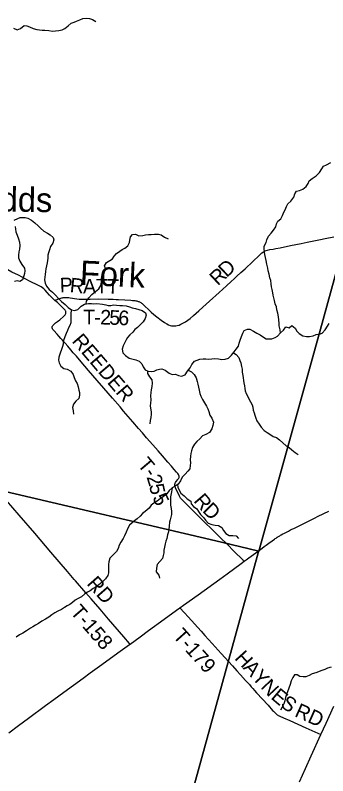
# Model space of a CAD drawing. Extents: x 1442749 to 1756758, y 235267 to 677782.
# Drawn here: x 1566168 to 1572579, y 484946 to 500562 of the extents above; entities that cross this region are included whole.
import ezdxf

# ---------------------------------------------------------------- set-up
doc = ezdxf.new("R2010")
doc.units = 0
for name, color, linetype in [('GM_X_County_Road', 7, 'Continuous'), ('GM_X_Minor_River', 7, 'Continuous'), ('GM_X_Minor_River_Text', 7, 'Continuous'), ('GM_X_Township', 7, 'Continuous'), ('GM_X_Township_Road', 7, 'Continuous'), ('GM_X_Township_Road_Text', 7, 'Continuous'), ('GM_X_US_Route', 7, 'Continuous')]:
    doc.layers.add(name, color=color, linetype=linetype)

msp = doc.modelspace()

# ---------------------------------------------------------------- linework, layer by layer
at = {"layer": 'GM_X_County_Road'}
for points in [[(1571367, 489719), (1571435, 489770), (1571483, 489803), (1571502, 489817), (1571518, 489828), (1571533, 489838), (1571539, 489842), (1571544, 489845), (1571557, 489853), (1571570, 489861), (1571580, 489867), (1571594, 489875), (1571609, 489883), (1571625, 489892), (1571660, 489912), (1571690, 489929), (1571718, 489944), (1571743, 489957), (1571770, 489971), (1571794, 489984), (1571817, 489995), (1571840, 490007), (1571879, 490026), (1572100, 490135), (1572305, 490236), (1572384, 490275), (1572599, 490381)], [(1570863, 489349), (1570904, 489379), (1570960, 489420), (1571052, 489488), (1571150, 489559), (1571232, 489620), (1571274, 489651), (1571315, 489681), (1571367, 489719)], [(1569547, 488394), (1569621, 488449), (1569918, 488660), (1570366, 488986), (1570515, 489094), (1570801, 489304), (1570863, 489349)], [(1568523, 487651), (1568730, 487801), (1568902, 487927), (1569226, 488161), (1569479, 488344), (1569547, 488394)], [(1566036, 485831), (1566237, 485980), (1566438, 486126), (1566790, 486386), (1566959, 486510), (1567168, 486663), (1567563, 486950), (1567708, 487058), (1567945, 487229), (1568275, 487472), (1568512, 487643), (1568523, 487651)]]:
    msp.add_lwpolyline(points, dxfattribs=at)
at = {"layer": 'GM_X_Minor_River'}
for points in [[(1566134, 500299), (1566209, 500259), (1566278, 500289), (1566349, 500350), (1566409, 500345), (1566462, 500324), (1566534, 500291), (1566608, 500270), (1566666, 500263), (1566722, 500256), (1566778, 500256), (1566858, 500247), (1566930, 500236), (1566996, 500241), (1567062, 500248), (1567132, 500261), (1567183, 500288), (1567253, 500347), (1567316, 500397), (1567375, 500420), (1567425, 500437), (1567495, 500468), (1567552, 500494), (1567624, 500503), (1567688, 500494), (1567750, 500471), (1567821, 500432)], [(1571607, 494037), (1571599, 494102), (1571584, 494181), (1571579, 494231), (1571572, 494309), (1571565, 494372), (1571554, 494442), (1571535, 494512), (1571524, 494571), (1571501, 494637), (1571486, 494707), (1571473, 494758), (1571461, 494812), (1571452, 494864), (1571435, 494931), (1571426, 494983), (1571415, 495049), (1571408, 495113), (1571390, 495172), (1571374, 495246), (1571358, 495310), (1571347, 495371), (1571332, 495453), (1571317, 495525), (1571304, 495586), (1571289, 495648), (1571282, 495698), (1571273, 495769), (1571276, 495821), (1571313, 495896), (1571328, 495950), (1571363, 496026), (1571418, 496089), (1571463, 496145), (1571510, 496216), (1571529, 496276), (1571551, 496334), (1571614, 496379), (1571653, 496449), (1571680, 496517), (1571707, 496568), (1571732, 496632), (1571761, 496688), (1571824, 496747), (1571885, 496823), (1571902, 496893), (1571937, 496948), (1572001, 496965), (1572068, 496991), (1572136, 497044), (1572173, 497105), (1572196, 497159), (1572259, 497212), (1572342, 497267), (1572407, 497329), (1572454, 497410), (1572489, 497462), (1572553, 497489), (1572642, 497540)], [(1566148, 496352), (1566221, 496385), (1566271, 496406), (1566321, 496411), (1566375, 496411), (1566427, 496392), (1566503, 496351), (1566572, 496300), (1566639, 496239), (1566684, 496188), (1566756, 496127), (1566827, 496086), (1566883, 496055), (1566944, 496000), (1566963, 495950), (1566940, 495882), (1566891, 495816), (1566868, 495748), (1566849, 495685), (1566839, 495633), (1566838, 495572), (1566822, 495480), (1566797, 495357), (1566790, 495302), (1566779, 495236), (1566772, 495184), (1566771, 495130), (1566782, 495062), (1566809, 494996), (1566864, 494929), (1566932, 494872), (1566995, 494811), (1567052, 494746), (1567117, 494683), (1567190, 494620), (1567255, 494559), (1567321, 494510), (1567383, 494497), (1567455, 494522), (1567522, 494587), (1567591, 494628), (1567671, 494641), (1567729, 494640), (1567781, 494638), (1567843, 494641), (1567955, 494631), (1568023, 494618), (1568077, 494605), (1568131, 494605), (1568181, 494612), (1568243, 494611), (1568311, 494604), (1568367, 494600), (1568441, 494592), (1568511, 494576), (1568565, 494557), (1568637, 494542), (1568702, 494519), (1568774, 494496), (1568839, 494453), (1568851, 494400), (1568834, 494333), (1568791, 494269), (1568728, 494202), (1568673, 494150), (1568622, 494109), (1568581, 494057), (1568517, 493998), (1568474, 493947), (1568443, 493895)], [(1566164, 496221), (1566174, 496171), (1566183, 496113), (1566208, 496044), (1566237, 495972), (1566252, 495901), (1566261, 495831), (1566252, 495761), (1566243, 495701), (1566234, 495635), (1566237, 495583), (1566264, 495512), (1566305, 495443), (1566358, 495366), (1566365, 495312), (1566359, 495260), (1566342, 495208), (1566319, 495131), (1566262, 495093), (1566208, 495106), (1566156, 495095)], [(1567622, 494633), (1567632, 494690), (1567677, 494757), (1567736, 494827), (1567813, 494886), (1567880, 494941), (1567927, 495012), (1567940, 495084), (1567937, 495151), (1567943, 495203), (1567962, 495254), (1568005, 495310), (1568016, 495364), (1568001, 495418), (1568040, 495484), (1568106, 495523), (1568161, 495560), (1568198, 495616), (1568248, 495668), (1568311, 495715), (1568364, 495754), (1568416, 495781), (1568479, 495825), (1568510, 495892), (1568517, 495946), (1568534, 496010), (1568573, 496062), (1568633, 496067), (1568702, 496030), (1568784, 496039), (1568841, 496052), (1568899, 496058), (1568955, 496061), (1569023, 496068), (1569107, 496067), (1569161, 496052), (1569232, 496007), (1569302, 495972)], [(1567321, 494510), (1567308, 494452), (1567305, 494379), (1567308, 494309), (1567307, 494245), (1567290, 494193), (1567263, 494141), (1567237, 494086), (1567214, 494024), (1567185, 493956), (1567160, 493884), (1567152, 493810), (1567140, 493758), (1567119, 493696), (1567088, 493623), (1567062, 493543), (1567052, 493481), (1567067, 493427), (1567100, 493354), (1567167, 493311), (1567235, 493294), (1567307, 493255), (1567356, 493188), (1567377, 493122), (1567406, 493055), (1567435, 493003), (1567460, 492930), (1567475, 492864), (1567484, 492814), (1567488, 492763), (1567469, 492695), (1567410, 492640), (1567363, 492573), (1567344, 492505), (1567355, 492436), (1567364, 492370)], [(1568443, 493895), (1568414, 493843), (1568379, 493776), (1568362, 493704), (1568373, 493633), (1568430, 493572), (1568506, 493519), (1568557, 493504), (1568639, 493483), (1568709, 493456), (1568766, 493405), (1568789, 493341), (1568830, 493282), (1568892, 493253), (1568966, 493246), (1569016, 493254), (1569075, 493279), (1569125, 493296), (1569175, 493302), (1569245, 493277), (1569324, 493213), (1569388, 493182), (1569452, 493194), (1569517, 493167), (1569579, 493152), (1569652, 493181), (1569699, 493252), (1569756, 493322), (1569793, 493393), (1569846, 493459), (1569900, 493480), (1569953, 493498), (1570021, 493509), (1570079, 493506), (1570133, 493501), (1570199, 493510), (1570253, 493511), (1570337, 493506), (1570407, 493495), (1570477, 493500), (1570540, 493518), (1570607, 493581), (1570658, 493648), (1570700, 493702), (1570747, 493765), (1570760, 493827), (1570779, 493893), (1570810, 493965), (1570837, 494035), (1570864, 494086), (1570933, 494116), (1570983, 494113), (1571054, 494076), (1571124, 494031), (1571191, 493998), (1571257, 493953), (1571316, 493920), (1571368, 493915), (1571432, 493916), (1571497, 493942), (1571547, 493971), (1571608, 494038), (1571671, 494095), (1571718, 494161), (1571788, 494146), (1571841, 494189), (1571910, 494136), (1571947, 494076), (1571992, 494025), (1572064, 493980), (1572144, 493965), (1572206, 493966), (1572276, 493981), (1572338, 494006), (1572411, 494013), (1572461, 494035), (1572522, 494100), (1572571, 494179), (1572610, 494235)], [(1570643, 493629), (1570697, 493598), (1570756, 493531), (1570775, 493474), (1570792, 493424), (1570809, 493352), (1570821, 493297), (1570826, 493231), (1570837, 493163), (1570859, 493014), (1570868, 492954), (1570877, 492898), (1570884, 492847), (1570903, 492797), (1570937, 492732), (1570968, 492674), (1570995, 492623), (1571026, 492561), (1571039, 492511), (1571051, 492456), (1571068, 492398), (1571081, 492348), (1571100, 492289), (1571125, 492233), (1571171, 492162), (1571214, 492101), (1571271, 492036), (1571338, 491997), (1571408, 491946), (1571459, 491909), (1571525, 491889), (1571586, 491846), (1571655, 491780), (1571723, 491721), (1571786, 491689), (1571838, 491638), (1571907, 491583), (1571968, 491542)], [(1569717, 493274), (1569781, 493239), (1569838, 493182), (1569879, 493114), (1569898, 493041), (1569913, 492989), (1569928, 492925), (1569940, 492866), (1569956, 492794), (1569974, 492742), (1570007, 492671), (1570050, 492602), (1570091, 492533), (1570116, 492479), (1570137, 492427), (1570162, 492352), (1570201, 492287), (1570232, 492203), (1570223, 492139), (1570200, 492071), (1570151, 491997), (1570080, 491952), (1570012, 491925), (1569953, 491864), (1569890, 491807), (1569845, 491753), (1569806, 491683), (1569785, 491620), (1569770, 491566), (1569764, 491508), (1569757, 491436), (1569760, 491373), (1569759, 491317), (1569746, 491251), (1569711, 491200), (1569654, 491138), (1569591, 491075), (1569560, 491005), (1569509, 490934), (1569448, 490895), (1569386, 490859), (1569327, 490804), (1569278, 490736), (1569201, 490675), (1569148, 490638), (1569080, 490583), (1569011, 490540), (1568954, 490502), (1568913, 490439), (1568836, 490370), (1568780, 490328), (1568733, 490277), (1568672, 490224), (1568613, 490180), (1568563, 490141), (1568512, 490091), (1568475, 490032), (1568442, 489946), (1568411, 489870), (1568380, 489819), (1568335, 489745), (1568302, 489681), (1568277, 489610), (1568246, 489552), (1568173, 489479), (1568108, 489417), (1568089, 489339), (1568082, 489287), (1568081, 489237), (1568082, 489183), (1568079, 489113), (1568064, 489055), (1568017, 488988), (1567952, 488924), (1567884, 488869), (1567827, 488828), (1567768, 488793), (1567702, 488745), (1567647, 488714), (1567594, 488679), (1567526, 488622), (1567459, 488588), (1567396, 488555), (1567342, 488504), (1567287, 488464), (1567233, 488435), (1567176, 488402), (1567117, 488362), (1567045, 488327), (1566980, 488294), (1566918, 488249), (1566859, 488200), (1566786, 488164), (1566714, 488123), (1566647, 488072), (1566586, 488041), (1566530, 488006), (1566479, 487974), (1566398, 487919), (1566326, 487876), (1566253, 487837)], [(1568878, 493260), (1568883, 493203), (1568920, 493139), (1568968, 493076), (1568979, 493004), (1568970, 492936), (1568957, 492868), (1568948, 492814), (1568945, 492744), (1568952, 492665), (1568945, 492593), (1568938, 492541), (1568943, 492491), (1568958, 492419), (1568959, 492368), (1568946, 492302), (1568935, 492238), (1568930, 492172)], [(1569384, 490857), (1569373, 490779), (1569351, 490675), (1569352, 490619), (1569353, 490561), (1569353, 490505), (1569366, 490431), (1569375, 490370), (1569370, 490310), (1569361, 490258), (1569344, 490202), (1569329, 490150), (1569322, 490074), (1569317, 490008), (1569311, 489956), (1569294, 489896), (1569275, 489820), (1569260, 489763), (1569243, 489709), (1569228, 489641), (1569219, 489577), (1569216, 489525), (1569205, 489467), (1569187, 489409), (1569134, 489343), (1569079, 489282), (1569064, 489206), (1569056, 489132), (1569114, 489067), (1569129, 489001)], [(1569496, 490925), (1569506, 490872), (1569525, 490821), (1569568, 490749), (1569632, 490694), (1569695, 490633), (1569768, 490581), (1569775, 490527), (1569823, 490474), (1569896, 490427), (1569929, 490371), (1569970, 490312), (1570034, 490243), (1570073, 490192), (1570128, 490134), (1570200, 490103), (1570266, 490094), (1570334, 490085), (1570405, 490042), (1570438, 489985), (1570491, 489922), (1570559, 489881), (1570633, 489882), (1570701, 489875), (1570746, 489820)], [(1566253, 487837), (1566186, 487794)], [(1572646, 487177), (1572573, 487154), (1572517, 487128), (1572438, 487099), (1572388, 487078), (1572332, 487063), (1572259, 487038), (1572195, 487002), (1572128, 486979), (1572072, 486976), (1572008, 486985), (1571951, 487018), (1571897, 487019), (1571860, 486965), (1571831, 486893), (1571808, 486821), (1571783, 486743), (1571750, 486668), (1571729, 486612), (1571714, 486550), (1571697, 486486), (1571674, 486426), (1571641, 486356), (1571608, 486291)]]:
    msp.add_lwpolyline(points, dxfattribs=at)
at = {"layer": 'GM_X_Township'}
for points in [[(1574679, 502300), (1573762, 498986), (1572955, 496035), (1572410, 494039), (1571164, 489560), (1570397, 489740), (1565725, 490836), (1562240, 491653), (1557897, 492683), (1551075, 494300), (1546805, 495313), (1545138, 495708), (1545013, 495738), (1545078, 496425), (1545353, 499331), (1545798, 504044)], [(1600346, 496373), (1594192, 493386), (1589677, 491347), (1589558, 491294), (1586641, 487791), (1583852, 484442), (1583514, 484036), (1582700, 483060), (1581429, 481533), (1577422, 482442), (1577047, 482527), (1571453, 483622), (1569628, 483980), (1570529, 487256), (1571154, 489524), (1571164, 489560), (1572410, 494039), (1572955, 496035), (1573762, 498986), (1574679, 502300)], [(1565725, 490836), (1570397, 489740), (1571164, 489560), (1571154, 489524), (1570529, 487256), (1569628, 483980), (1566747, 484545), (1565221, 479519)]]:
    msp.add_lwpolyline(points, dxfattribs=at)
at = {"layer": 'GM_X_Township_Road'}
for points in [[(1566982, 494706), (1567002, 494715), (1567026, 494725), (1567054, 494736), (1567085, 494746), (1567102, 494752), (1567123, 494758), (1567136, 494761), (1567152, 494764), (1567169, 494766), (1567187, 494768), (1567214, 494769), (1567247, 494767), (1567270, 494765), (1567296, 494762), (1567429, 494740), (1567481, 494734), (1567510, 494733), (1567546, 494732), (1567707, 494735), (1567881, 494739), (1568071, 494735), (1568145, 494733), (1568178, 494732), (1568240, 494728), (1568286, 494726), (1568419, 494718), (1568542, 494709), (1568572, 494707), (1568604, 494704), (1568624, 494701), (1568641, 494699), (1568662, 494695), (1568676, 494691), (1568692, 494686), (1568706, 494681), (1568719, 494675), (1568731, 494669), (1568745, 494660), (1568757, 494651), (1568772, 494641), (1568792, 494624), (1568835, 494583), (1568894, 494525), (1568957, 494464), (1569014, 494414), (1569073, 494368), (1569162, 494301), (1569232, 494253), (1569280, 494224), (1569314, 494207), (1569345, 494194), (1569373, 494187), (1569401, 494182), (1569434, 494182), (1569463, 494184), (1569492, 494190), (1569529, 494201), (1569568, 494217), (1569609, 494237), (1569657, 494265), (1569706, 494298), (1569758, 494338), (1569823, 494393), (1569932, 494491), (1570015, 494566), (1570154, 494691), (1570350, 494870), (1570426, 494938), (1570502, 495006), (1570597, 495095), (1570657, 495151), (1570712, 495203), (1570792, 495276), (1570882, 495357), (1571043, 495507), (1571170, 495626), (1571228, 495680), (1571257, 495702), (1571282, 495718), (1571312, 495732), (1571341, 495740), (1571389, 495750), (1571460, 495761), (1571510, 495771), (1571602, 495788), (1571817, 495832), (1572033, 495875), (1572155, 495899), (1572428, 495954), (1572522, 495974), (1572705, 496010)], [(1566982, 494706), (1566951, 494734), (1566910, 494771), (1566868, 494815), (1566822, 494871), (1566780, 494918), (1566755, 494943), (1566729, 494963), (1566699, 494983), (1566644, 495011), (1566460, 495102), (1566232, 495222), (1566101, 495289), (1565967, 495360), (1565727, 495484), (1565551, 495576), (1565473, 495618), (1565352, 495681), (1565236, 495741), (1565099, 495815), (1564964, 495887), (1564938, 495900), (1564912, 495914), (1564897, 495922)], [(1570228, 489982), (1570031, 490176), (1569779, 490425), (1569706, 490496), (1569617, 490582), (1569584, 490618), (1569561, 490648), (1569537, 490687), (1569507, 490746), (1569476, 490812), (1569456, 490860), (1569447, 490889), (1569444, 490901), (1569442, 490917), (1569443, 490934), (1569447, 490951), (1569454, 490966), (1569467, 490985), (1569500, 491026), (1569512, 491042), (1569522, 491058), (1569527, 491073), (1569529, 491085), (1569528, 491101), (1569524, 491116), (1569516, 491133), (1569504, 491152), (1569479, 491182), (1569430, 491235), (1569371, 491301), (1569295, 491387), (1569186, 491514), (1569098, 491615), (1568990, 491739), (1568863, 491885), (1568777, 491984), (1568698, 492076), (1568580, 492213), (1568438, 492377), (1568389, 492434), (1568318, 492520), (1568163, 492698), (1567674, 493268), (1567520, 493444), (1567422, 493558), (1567355, 493633), (1567308, 493689), (1567244, 493764), (1567191, 493826), (1567159, 493863), (1567138, 493888), (1567106, 493923), (1567062, 493974), (1567026, 494016), (1566961, 494088), (1566941, 494111), (1566932, 494125), (1566929, 494130), (1566927, 494137), (1566925, 494144), (1566924, 494153), (1566924, 494161), (1566926, 494169), (1566929, 494178), (1566937, 494190), (1566945, 494200), (1566957, 494211), (1566996, 494243), (1567033, 494273), (1567080, 494310), (1567161, 494377), (1567184, 494400), (1567192, 494410), (1567201, 494424), (1567205, 494434), (1567208, 494448), (1567208, 494465), (1567206, 494480), (1567204, 494488), (1567201, 494494), (1567190, 494509), (1567172, 494529), (1567098, 494600), (1567035, 494660), (1566982, 494706)], [(1568523, 487651), (1568512, 487665), (1568396, 487802), (1568084, 488162), (1567907, 488368), (1567724, 488579), (1567617, 488703), (1567406, 488949), (1567380, 488979), (1567243, 489139), (1566901, 489536), (1566567, 489925), (1566249, 490296), (1565987, 490598), (1565746, 490880), (1565628, 491015)], [(1570863, 489349), (1570853, 489361), (1570845, 489372), (1570837, 489381), (1570830, 489389), (1570668, 489547), (1570505, 489709), (1570386, 489826), (1570228, 489982)], [(1569547, 488394), (1569640, 488290), (1569714, 488209), (1569980, 487915), (1570060, 487828), (1570209, 487662), (1570394, 487458), (1570624, 487202)], [(1570624, 487202), (1570716, 487100)], [(1570716, 487100), (1570789, 487019), (1570894, 486902), (1570970, 486819), (1571009, 486775), (1571042, 486739), (1571079, 486698), (1571120, 486652), (1571354, 486395), (1571448, 486289), (1571462, 486274), (1571477, 486258), (1571492, 486243), (1571505, 486229), (1571519, 486217), (1571527, 486210), (1571534, 486204), (1571542, 486199), (1571553, 486192), (1571564, 486185), (1571582, 486177), (1571596, 486169), (1571670, 486135), (1571800, 486079), (1572131, 485932), (1572438, 485791)]]:
    msp.add_lwpolyline(points, dxfattribs=at)
at = {"layer": 'GM_X_US_Route'}
msp.add_lwpolyline([(1571999, 484821), (1572122, 485096), (1572241, 485356), (1572438, 485791), (1572544, 486025), (1572703, 486378)], dxfattribs=at)

# ---------------------------------------------------------------- texts
at = {"layer": 'GM_X_Minor_River_Text'}
for s, rotation, p in [('Todds', 359.0438, (1565066, 496548)), ('Fork', 357.349, (1567486, 495027))]:
    msp.add_text(s, height=500, rotation=rotation, dxfattribs=at).set_placement(p)
at = {"layer": 'GM_X_Township_Road_Text'}
for s, rotation, p in [('D', 43.6043, (1570506, 495164)), ('R', 42.9269, (1570323, 494994)), ('P', 2.1291, (1567087, 494868)), ('R', 353.9626, (1567278, 494876)), ('A', 0.1952, (1567559, 494848)), ('T', 359.5971, (1567822, 494849)), ('T', 358.1311, (1568044, 494847)), ('T', 359.9571, (1567563, 494214)), ('2', 358.8551, (1567909, 494213)), ('5', 357.944, (1568093, 494209)), ('6', 357.194, (1568276, 494203)), ('-', 359.6331, (1567787, 494214)), ('REEDER', 310.5057, (1567317, 493865)), ('T', 310.2413, (1568661, 491327)), ('2', 286.957, (1568859, 491082)), ('-', 304.0603, (1568801, 491163)), ('5', 282.178, (1568912, 490912)), ('5', 295.2093, (1568974, 490661)), ('R', 310.6656, (1569812, 490583)), ('D', 315.6542, (1569992, 490375)), ('RD', 311.237, (1567620, 488882)), ('T-158', 310.8441, (1567282, 488298)), ('T-179', 311.8233, (1569386, 487807)), ('H', 312.1294, (1570652, 487351)), ('A', 312.1328, (1570829, 487155)), ('Y', 312.1294, (1571006, 486960)), ('N', 313.2605, (1571187, 486759)), ('E', 319.8441, (1571395, 486541)), ('S', 324.693, (1571589, 486379)), ('RD', 335.8376, (1571881, 486174))]:
    msp.add_text(s, height=300, rotation=rotation, dxfattribs=at).set_placement(p)

doc.saveas('drawing.dxf')
